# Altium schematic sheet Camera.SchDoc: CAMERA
size A4; Date: Not used; ApprovedBy: Not used; CheckedBy: Not used; Author: Not used; CompanyName: STMicroelectronics; DrawnBy: Not used; Engineer: Not used; Organization: Not used; Address1: Not used; Address2: Not used; Address3: Not used; Address4: Not used; DocumentNumber: 10; Revision: Not used; SheetNumber: 10; SheetTotal: 16
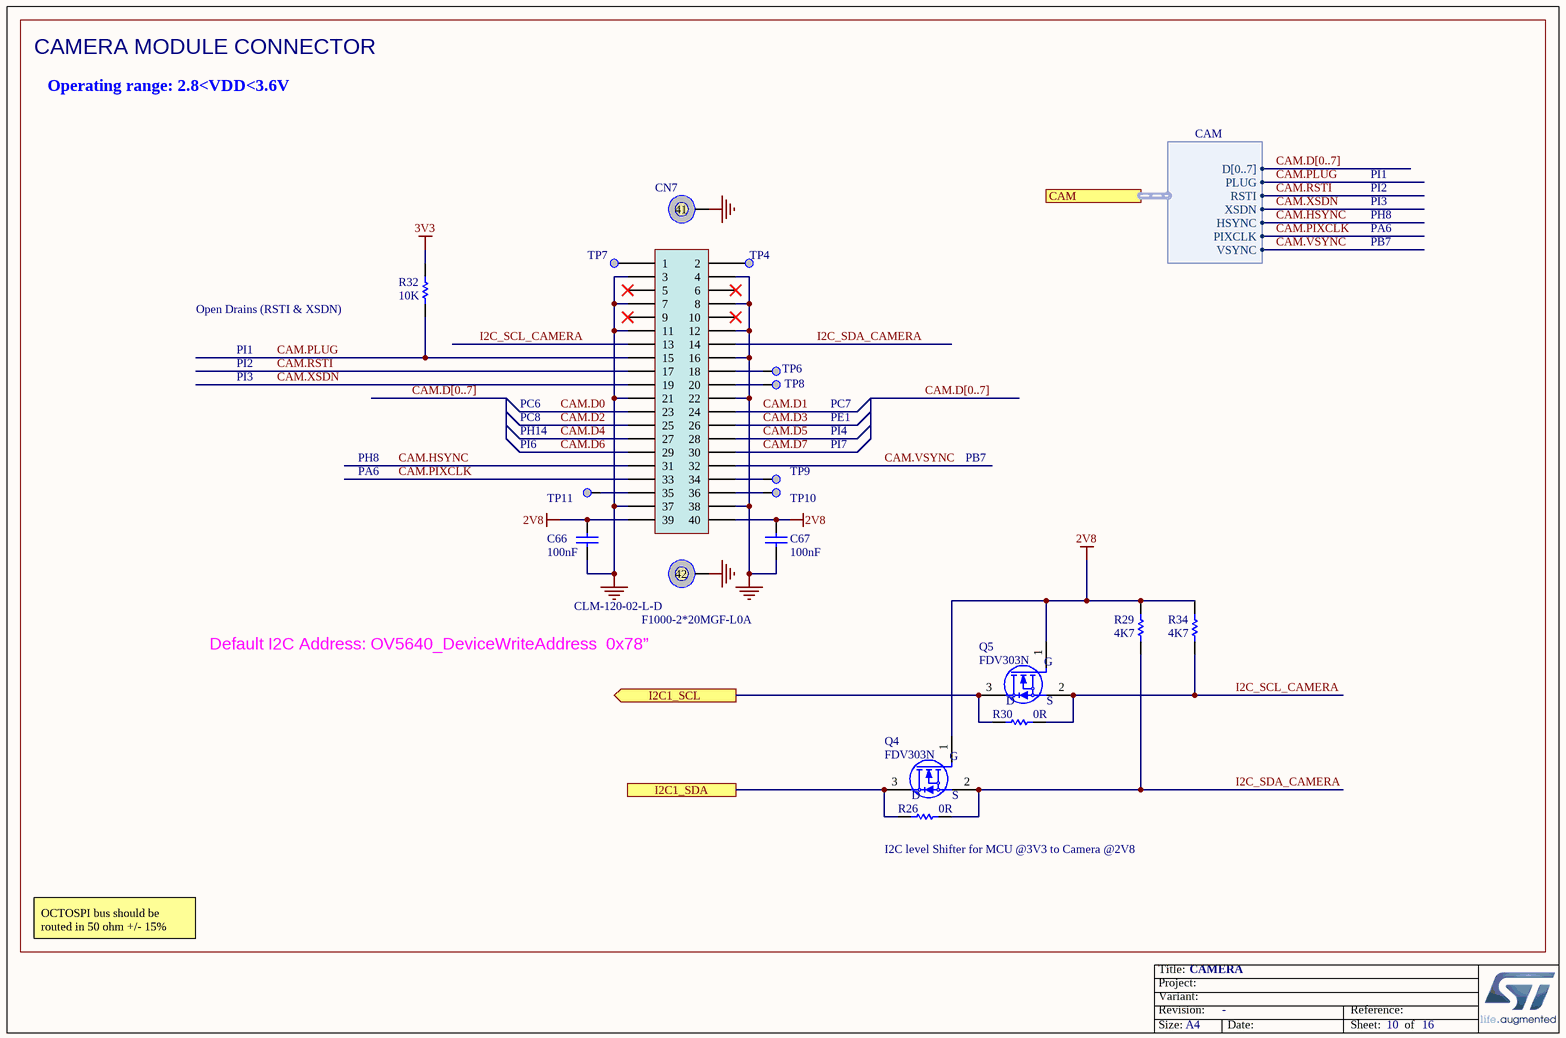
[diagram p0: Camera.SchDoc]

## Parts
C66  value 100nF  [C0402]
C67  value 100nF  [C0402]
CN7  value CLM-120-02-L-D  [CON_SAMTEC_CLM-120-02-L-D_Reverse-to-Camera]
Q4  value FDV303N  [MOS_SOT23]  (hidden comment: BSN20)
Q5  value FDV303N  [MOS_SOT23]  (hidden comment: BSN20)
R26  value 0R  [R0603]  (hidden comment: Resistor)
R29  value 4K7  [R0402]
R30  value 0R  [R0603]  (hidden comment: Resistor)
R32  value 10K  [R0603]
R34  value 4K7  [R0402]
TP4  Test Point  [TP_SMD_1MM]  (value not drawn)  (no BOM)
TP6  Test Point  [TP_SMD_1MM]  (value not drawn)  (no BOM)
TP7  Test Point  [TP_SMD_1MM]  (value not drawn)  (no BOM)
TP8  Test Point  [TP_SMD_1MM]  (value not drawn)  (no BOM)
TP9  Test Point  [TP_SMD_1MM]  (value not drawn)  (no BOM)
TP10  Test Point  [TP_SMD_1MM]  (value not drawn)  (no BOM)
TP11  Test Point  [TP_SMD_1MM]  (value not drawn)  (no BOM)

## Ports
CAM (harness CAM), I2C1_SCL (out), I2C1_SDA

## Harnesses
CAM: D[0..7], PLUG, XSDN, HSYNC, PIXCLK, VSYNC, RSTI

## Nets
2V8: C66.2 C67.2 CN7.39 CN7.40 Q4.1(G) Q5.1(G) R29.2 R34.2
3V3: R32.2
GND: C66.1 C67.1 CN7.3 CN7.4 CN7.7 CN7.8 CN7.11 CN7.12 CN7.16 CN7.21 CN7.22 CN7.37 CN7.38 CN7.41 CN7.42
CAM.D0: CN7.23
CAM.D1: CN7.24
CAM.D2: CN7.25
CAM.D3: CN7.26
CAM.D4: CN7.27
CAM.D5: CN7.28
CAM.D6: CN7.29
CAM.D7: CN7.30
CAM.HSYNC: CN7.31 ; port CAM.HSYNC
CAM.PIXCLK: CN7.33 ; port CAM.PIXCLK
CAM.PLUG: CN7.15 R32.1 ; port CAM.PLUG
CAM.RSTI: CN7.17 ; port CAM.RSTI
CAM.VSYNC: CN7.32 ; port CAM.VSYNC
CAM.XSDN: CN7.19 ; port CAM.XSDN
I2C1_SCL: Q5.3(D) R30.1 ; port I2C1_SCL
I2C1_SDA: Q4.3(D) R26.1 ; port I2C1_SDA
I2C_SCL_CAMERA: CN7.13 Q5.2(S) R30.2 R34.1
I2C_SDA_CAMERA: CN7.14 Q4.2(S) R26.2 R29.1
NetCN7_1: CN7.1 TP7.1
NetCN7_2: CN7.2 TP4.1
NetCN7_18: CN7.18 TP6.1
NetCN7_20: CN7.20 TP8.1
NetCN7_34: CN7.34 TP9.1
NetCN7_35: CN7.35 TP11.1
NetCN7_36: CN7.36 TP10.1

Not connected (* = marked no-connect by the designer): CN7 5* 6* 9* 10*

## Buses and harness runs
bus CAM.D[0..7]

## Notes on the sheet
- CAMERA MODULE CONNECTOR
- Operating range: 2.8<VDD<3.6V
- PI1
- PI2
- PI3
- PH8
- PA6
- PB7
- Open Drains (RSTI & XSDN)
- PC6
- PC8
- PH14
- PI6
- PC7
- PE1
- PI4
- PI7
- Default I2C Address: OV5640_DeviceWriteAddress  0x78”
- (near CN7) F1000-2*20MGF-L0A
- (near R26) I2C level Shifter for MCU @3V3 to Camera @2V8
- OCTOSPI bus should be routed in 50 ohm +/- 15%

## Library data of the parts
C66 C67 = MCD-00006: Capacitor, MLCC, 100nF, 16V, X7R, 10%, 0402, T=0.5mm; Manufacturer_Part_Number: CC0402KRX7R7BB104; Manufacturer: YAGEO; Alternate_Manufacturer_Part_Number: GCM155R71C104KA55D; Alternate_Manufacturer: MURATA; Provided_By: SUBCO; ECCN_US: EAR99; ECCN_EU: NEC
CN7 = MCD-00138: Socket, 20x2, 1.0mm, VR, SMT, Height 2.26mm. Symbol & Footprint dedicated to MB1183 & MB1379 camera modules (not in line with Samtec datasheet); Part_Type: Connector; Provided_By: SUBCO; ECCN_US: EAR99; ECCN_EU: NEC
Q4 Q5 = MCD-01164: N-channel Digital FET; Part_Type: IC; Manufacturer: FAIRCHILD; BMS_Part_Number: 9153036; Provided_By: SUBCO
R26 R30 = MCD-00056: Resistor,0R,0603,5%,1/10W; Manufacturer_Part_Number: RC0603JR-070RL; Manufacturer: YAGEO; Provided_By: SUBCO; ECCN_US: EAR99; ECCN_EU: NEC
R29 R34 = MCD-00065: Resistor,4K7,0402,1%,1/16W; Manufacturer_Part_Number: RC0402FR-074K7L; Manufacturer: YAGEO; Alternate_Manufacturer_Part_Number: RT0402FRE074K7L; Provided_By: SUBCO; ECCN_US: EAR99; ECCN_EU: NEC
R32 = MCD-00220: Resistor,10K,0603,1%,1/10W; Manufacturer_Part_Number: RC0603FR-0710KL; Manufacturer: YAGEO; Provided_By: Subcon; Initial_Board_Reference: MB1319
TP4 TP6-TP11 = MCD-00074: Test Point 1mm; Part_Type: Mechanical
